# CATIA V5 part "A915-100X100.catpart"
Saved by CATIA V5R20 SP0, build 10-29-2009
Part number: A915-100X100
Source: Unknown
Property "A": "0.000"
Property "ARTICLENO": "A915-100X100"
Property "BOMINFO": "A915-100X100"
Property "CODE": "A915-100X100"
Property "CREATOR": "CADENAS GmbH"
Property "D": "13.500"
Property "D1": "20.000"
Property "FORM": "B"
Property "L": "100.000"
Property "L1": "25.000"
Property "L2": "50.000"
Property "LINA": "A915-100X100"
Property "NB": "A915-100X100"
Property "NBSYN": "$CODE."
Property "NN": "A915"
Property "NT": "VDI 3357 Wear Plates, steel"
Property "SCREW": "M12x25"
Property "SUPPLIER": "CF"
Property "T": "13.000"
Property "W": "100.000"
Bounding box of the stored display mesh (mm): x 0 to 20, y 0 to 100, z -50 to 50
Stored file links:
  C:\Users\borellobunino\Desktop\3D X SITO CF\A915\GSB_OILLESS_G22501100100\CATIAV5\A915-100X100.catpart
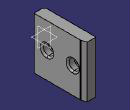
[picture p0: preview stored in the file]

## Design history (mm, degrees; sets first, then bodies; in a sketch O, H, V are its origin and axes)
Body1 "Geometry.1" (main body)
  Solid1 "A915-100X100.catpart": solid without history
